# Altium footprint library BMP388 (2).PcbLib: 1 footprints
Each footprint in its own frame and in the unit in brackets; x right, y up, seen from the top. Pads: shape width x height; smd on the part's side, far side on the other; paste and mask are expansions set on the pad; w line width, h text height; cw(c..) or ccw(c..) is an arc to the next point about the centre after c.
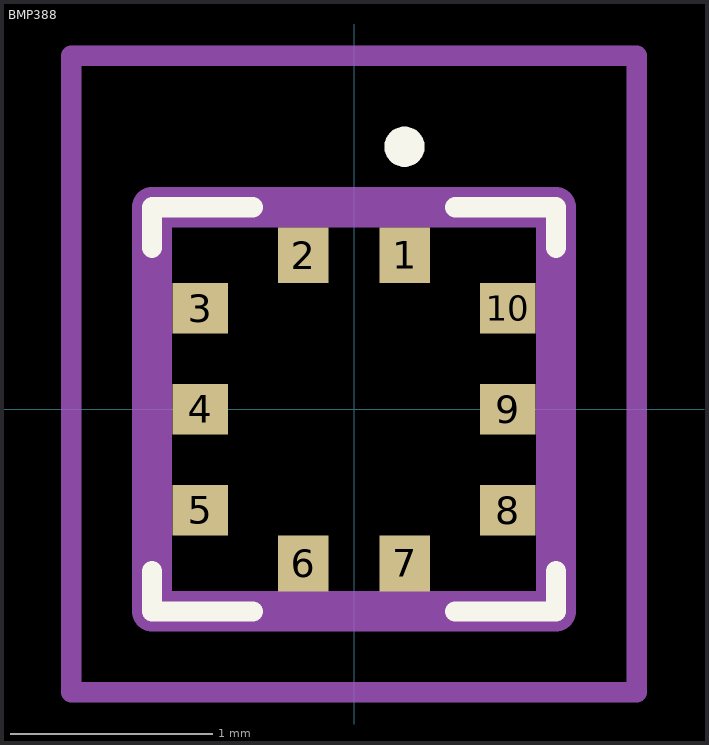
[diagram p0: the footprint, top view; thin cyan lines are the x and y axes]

## BMP388 [mm]
pads (10):
  rect 0.25x0.275 smd: 1(0.25,0.763) 2(-0.25,0.763) 6(-0.25,-0.763) 7(0.25,-0.763)
  rect 0.275x0.25 smd: 3(-0.762,0.5) 4(-0.762,0) 5(-0.762,-0.5) 8(0.762,-0.5) 9(0.762,0) 10(0.762,0.5)
Top Overlay:
  lines w0.1: -1,-0.8 -1,-1 -0.5,-1 ; -1,0.8 -1,1 -0.5,1 ; 0.5,-1 1,-1 1,-0.8 ; 0.5,1 1,1 1,0.8 ; 0.2,1.3 cw(c0.25,1.3) 0.3,1.3 cw(c0.25,1.3) 0.2,1.3
Mechanical 13:
  lines w0.2: -1,-1 1,-1 1,1 -1,1 -1,-1
Mechanical 15:
  lines w0.1: -1.4,-1.4 1.4,-1.4 1.4,1.75 -1.4,1.75 -1.4,-1.4
3D body "BMP388--3DModel-STEP-56544.STEP": height 0.8, standoff 0, extent -1,-1.025 1,0.975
